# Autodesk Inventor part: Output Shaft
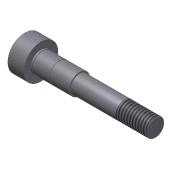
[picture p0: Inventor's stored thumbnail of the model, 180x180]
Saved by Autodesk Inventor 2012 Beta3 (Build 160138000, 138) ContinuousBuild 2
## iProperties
Created: 2011-01
Part Number: Output Shaft
Material: Steel
Document SubType Name: Modeling
Designer: Beta-8540w
Density: 1 g/cm^3
CustomPartVersion: 1
Author: Beta-8540w
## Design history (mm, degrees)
sketch "Main Sketch"
  geometry: L1 (0, 0)-(95, 0) reference; L2 (0, 0)-(0, 12.5); L3 (12, 12.5)-(12, 7.5); L4 (0, 12.5)-(12, 12.5); L5 (40, 7.5)-(40, 6.5); L6 (12, 7.5)-(40, 7.5); L7 (95, 6.5)-(95, 0); L8 (40, 6.5)-(95, 6.5)
  constraints: 16 end point, 5 horizontal, 4 vertical
  dimensions: "d3" = 25 diameter of L4 L1 (derived); "d4" = 15 diameter of L6 L1 (derived); "d5" = 13 diameter of L8 L1 (derived)
revolve "Revolution1" sketch "Main Sketch" stored, may be unused: angle "d6" = 0 deg
node "Retaining Ring Groove1"
node "Retaining Ring Groove2"
chamfer "Chamfer2" distance "d10" = 0.5; stored, may be unused: second distance "d11" = 0.125, angle "d12" = 45 deg
thread "Thread1" dims "d13" = 22, "d14" = 0
node "Spur Gear Teeth1"
body "Solid1"
feature "iFeature27:1"
feature "iFeature27:2"
feature "Cut Gear"
other parameters: "d0" = 0, "d1" = 0, "d2" = 0
